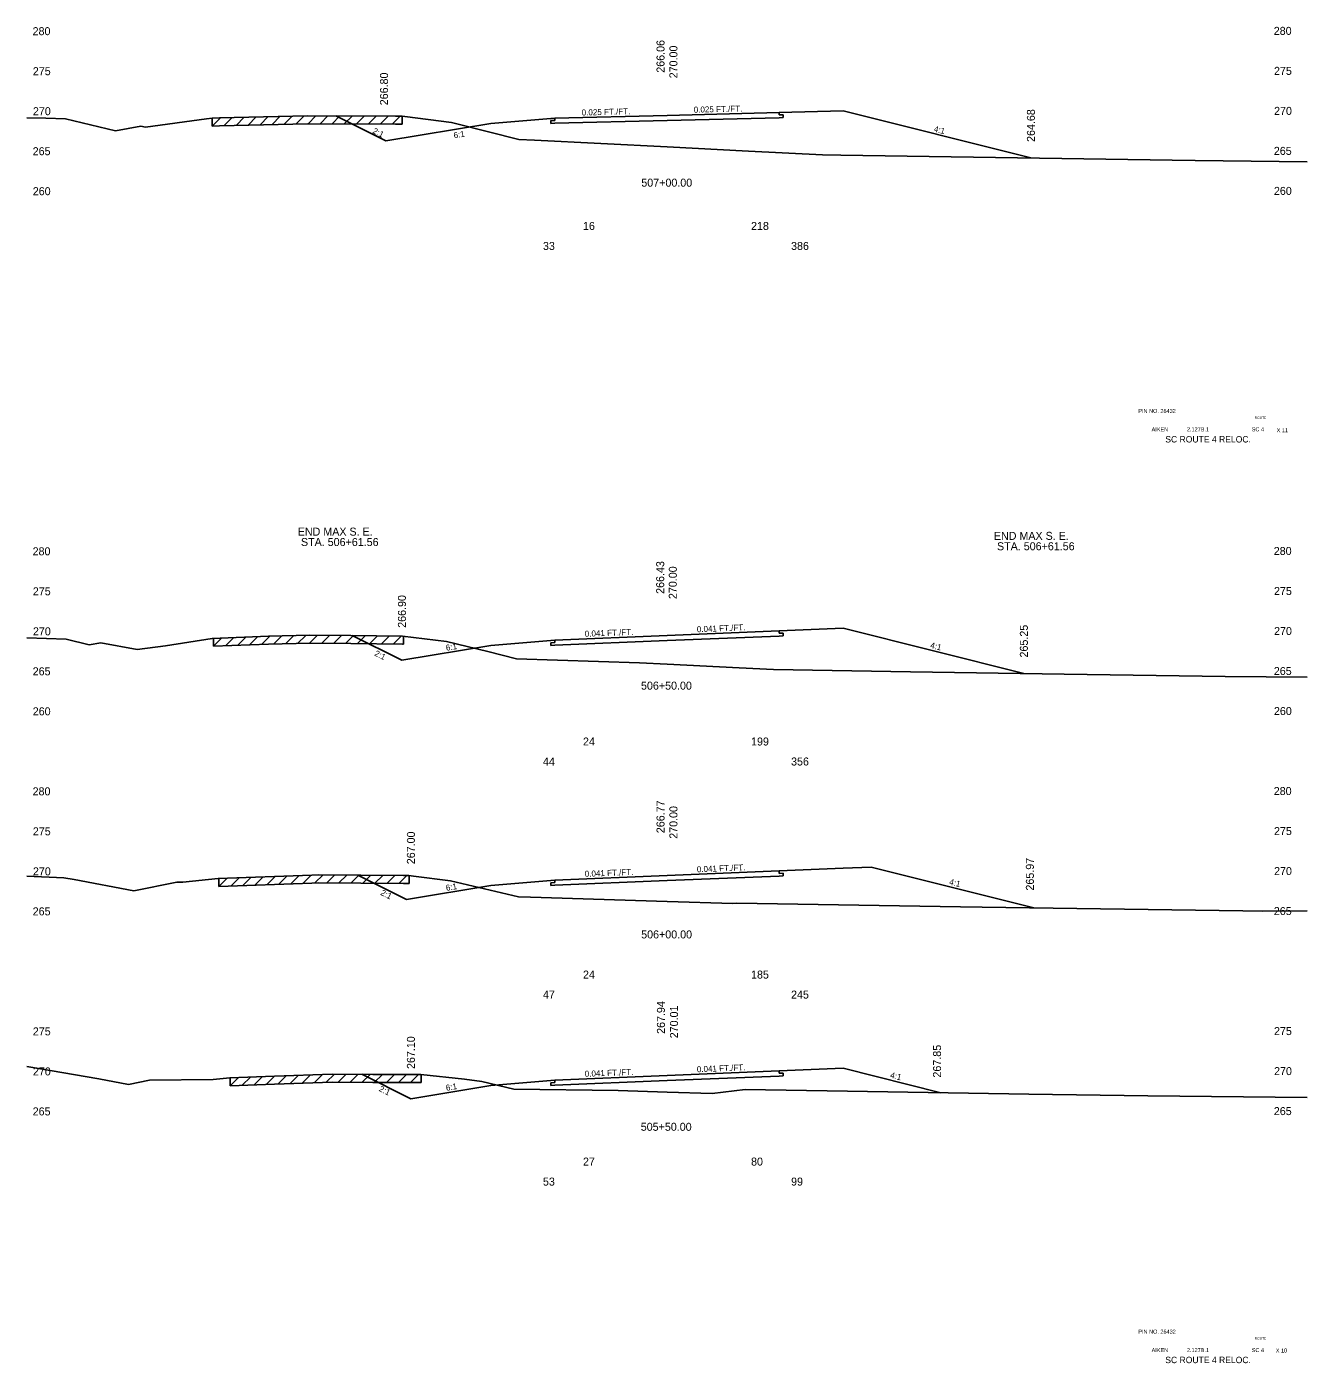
# Model space of a CAD drawing. Extents: x 2967 to 4323, y -3677 to -817.
# Drawn here: x 3188.8 to 3348.8, y -2545.8 to -2378.8 of the extents above; entities that cross this region are included whole.
import ezdxf

# ---------------------------------------------------------------- set-up
doc = ezdxf.new("R2010")
doc.units = 0
for name, color, linetype in [('Level 1', 7, 'Continuous'), ('Level 10', 7, 'Continuous'), ('Level 11', 7, 'Continuous'), ('Level 12', 7, 'Continuous'), ('Level 20', 7, 'Continuous'), ('Level 3', 7, 'Continuous'), ('Level 32', 7, 'Continuous'), ('Level 33', 7, 'Continuous'), ('Level 59', 7, 'Continuous'), ('Level 6', 7, 'Continuous'), ('Level 60', 7, 'Continuous'), ('Level 61', 7, 'Continuous'), ('Level 7', 7, 'Continuous')]:
    doc.layers.add(name, color=color, linetype=linetype)

msp = doc.modelspace()

# ---------------------------------------------------------------- linework, layer by layer
at = {"layer": 'Level 11'}
for p, q in [((3254.76, -2390.19), (3254.76, -2390.49)), ((3282.76, -2389.79), (3282.76, -2389.49)), ((3283.26, -2389.78), (3282.76, -2389.79)), ((3282.76, -2390.13), (3283.26, -2390.12)), ((3283.26, -2390.12), (3283.26, -2389.78)), ((3254.76, -2390.49), (3254.26, -2390.5)), ((3254.26, -2390.5), (3254.26, -2390.84)), ((3254.26, -2390.84), (3254.76, -2390.83)), ((3282.76, -2454.57), (3282.76, -2454.27)), ((3283.26, -2454.55), (3282.76, -2454.57)), ((3282.76, -2454.91), (3283.26, -2454.89)), ((3283.26, -2454.89), (3283.26, -2454.55)), ((3254.76, -2455.72), (3254.26, -2455.74)), ((3254.26, -2455.74), (3254.26, -2456.08)), ((3254.26, -2456.08), (3254.76, -2456.06)), ((3254.76, -2455.42), (3254.76, -2455.72)), ((3254.76, -2485.42), (3254.76, -2485.72)), ((3282.76, -2484.57), (3282.76, -2484.27)), ((3283.26, -2484.55), (3282.76, -2484.57)), ((3282.76, -2484.91), (3283.26, -2484.89)), ((3283.26, -2484.89), (3283.26, -2484.55)), ((3254.76, -2485.72), (3254.26, -2485.74)), ((3254.26, -2485.74), (3254.26, -2486.08)), ((3254.26, -2486.08), (3254.76, -2486.06)), ((3254.76, -2510.41), (3254.76, -2510.71)), ((3282.76, -2509.56), (3282.76, -2509.26)), ((3283.26, -2509.54), (3282.76, -2509.56)), ((3282.76, -2509.9), (3283.26, -2509.88)), ((3283.26, -2509.88), (3283.26, -2509.54)), ((3254.76, -2510.71), (3254.26, -2510.73)), ((3254.26, -2510.73), (3254.26, -2511.07)), ((3254.26, -2511.07), (3254.76, -2511.05))]:
    msp.add_line(p, q, dxfattribs=at)
at = {"layer": 'Level 12'}
for p, q in [((3282.76, -2390.13), (3268.76, -2390.48)), ((3268.76, -2390.48), (3254.76, -2390.83)), ((3282.76, -2454.91), (3268.76, -2455.48)), ((3268.76, -2455.48), (3254.76, -2456.06)), ((3282.76, -2484.91), (3268.76, -2485.48)), ((3268.76, -2485.48), (3254.76, -2486.06)), ((3268.76, -2510.47), (3254.76, -2511.05)), ((3282.76, -2509.9), (3268.76, -2510.47))]:
    msp.add_line(p, q, dxfattribs=at)
at = {"layer": 'Level 59'}
for p, q in [((3254.76, -2390.19), (3268.76, -2389.84)), ((3268.76, -2389.84), (3282.76, -2389.49)), ((3254.76, -2455.42), (3268.76, -2454.84)), ((3268.76, -2454.84), (3282.76, -2454.27)), ((3254.76, -2485.42), (3268.76, -2484.84)), ((3268.76, -2484.84), (3282.76, -2484.27)), ((3254.76, -2510.41), (3268.76, -2509.83)), ((3268.76, -2509.83), (3282.76, -2509.26))]:
    msp.add_line(p, q, dxfattribs=at)
at = {"layer": 'Level 6'}
for p, q in [((3246.76, -2390.86), (3254.76, -2390.19)), ((3282.76, -2389.49), (3290.76, -2389.29)), ((3282.76, -2454.27), (3290.76, -2453.94)), ((3246.76, -2456.08), (3254.76, -2455.42)), ((3246.76, -2486.08), (3254.76, -2485.42)), ((3282.76, -2484.27), (3290.76, -2483.94)), ((3290.76, -2483.94), (3294.26, -2483.8)), ((3246.76, -2511.07), (3254.76, -2510.41)), ((3282.76, -2509.26), (3290.76, -2508.93))]:
    msp.add_line(p, q, dxfattribs=at)
at = {"layer": 'Level 60'}
for p, q in [((3188.76, -2390.14), (3191.14, -2390.18)), ((3191.14, -2390.18), (3193.61, -2390.27)), ((3211.2, -2390.28), (3211.94, -2390.17)), ((3211.94, -2390.17), (3212.83, -2390.13)), ((3212.83, -2390.13), (3223.82, -2389.88)), ((3223.82, -2389.88), (3234.84, -2389.95)), ((3234.84, -2389.95), (3235.65, -2389.95)), ((3235.65, -2389.95), (3235.99, -2390)), ((3235.99, -2390), (3241.85, -2390.73)), ((3193.61, -2390.27), (3199.86, -2391.77)), ((3199.86, -2391.77), (3203.02, -2391.19)), ((3203.02, -2391.19), (3203.6, -2391.3)), ((3203.6, -2391.3), (3211.2, -2390.28)), ((3241.85, -2390.73), (3242.51, -2390.89)), ((3242.51, -2390.89), (3250.25, -2392.87)), ((3250.25, -2392.87), (3252.22, -2392.94)), ((3252.22, -2392.94), (3268.76, -2393.78)), ((3268.76, -2393.78), (3278.95, -2394.3)), ((3278.95, -2394.3), (3288.17, -2394.76)), ((3288.17, -2394.76), (3290.48, -2394.8)), ((3290.48, -2394.8), (3331.87, -2395.43)), ((3331.87, -2395.43), (3334.74, -2395.48)), ((3334.74, -2395.48), (3348.76, -2395.64)), ((3188.76, -2455.13), (3193.67, -2455.32)), ((3193.67, -2455.32), (3196.56, -2456.01)), ((3206.11, -2456.13), (3211.94, -2455.2)), ((3211.94, -2455.2), (3218.96, -2454.94)), ((3218.96, -2454.94), (3224.12, -2454.82)), ((3224.12, -2454.82), (3229.27, -2454.85)), ((3229.27, -2454.85), (3235.7, -2454.91)), ((3235.7, -2454.91), (3238.47, -2455.26)), ((3238.47, -2455.26), (3241.2, -2455.6)), ((3196.56, -2456.01), (3198.02, -2455.74)), ((3198.02, -2455.74), (3202.57, -2456.6)), ((3202.57, -2456.6), (3206.11, -2456.13)), ((3241.2, -2455.6), (3246.37, -2456.83)), ((3246.37, -2456.83), (3249.97, -2457.76)), ((3249.97, -2457.76), (3265.33, -2458.24)), ((3265.33, -2458.24), (3268.76, -2458.41)), ((3268.76, -2458.41), (3277.79, -2458.87)), ((3277.79, -2458.87), (3282.06, -2459.08)), ((3282.06, -2459.08), (3299.19, -2459.37)), ((3299.19, -2459.37), (3318.39, -2459.66)), ((3318.39, -2459.66), (3338.5, -2459.95)), ((3338.5, -2459.95), (3348.76, -2460.07)), ((3188.76, -2484.94), (3193.41, -2485.13)), ((3193.41, -2485.13), (3194.68, -2485.35)), ((3194.68, -2485.35), (3202.14, -2486.76)), ((3208.28, -2485.67), (3212.69, -2485.21)), ((3212.69, -2485.21), (3224.39, -2484.78)), ((3224.39, -2484.78), (3225.16, -2484.75)), ((3225.16, -2484.75), (3235.85, -2484.84)), ((3235.85, -2484.84), (3236.5, -2484.85)), ((3236.5, -2484.85), (3237.1, -2484.91)), ((3237.1, -2484.91), (3241.7, -2485.5)), ((3202.14, -2486.76), (3207.5, -2485.67)), ((3207.5, -2485.67), (3208.28, -2485.67)), ((3241.7, -2485.5), (3250.2, -2487.52)), ((3250.2, -2487.52), (3251.71, -2487.54)), ((3251.71, -2487.54), (3268.76, -2488.08)), ((3268.76, -2488.08), (3276.99, -2488.33)), ((3276.99, -2488.33), (3277.48, -2488.28)), ((3277.48, -2488.28), (3305.44, -2488.74)), ((3305.44, -2488.74), (3308.12, -2488.78)), ((3308.12, -2488.78), (3340.72, -2489.25)), ((3340.72, -2489.25), (3343.13, -2489.28)), ((3343.13, -2489.28), (3348.76, -2489.26)), ((3188.76, -2508.71), (3197.78, -2510.25)), ((3197.78, -2510.25), (3201.46, -2510.94)), ((3201.46, -2510.94), (3204.08, -2510.41)), ((3204.08, -2510.41), (3212.04, -2510.33)), ((3212.04, -2510.33), (3214.14, -2510.11)), ((3214.14, -2510.11), (3219.73, -2509.91)), ((3219.73, -2509.91), (3226.93, -2509.65)), ((3226.93, -2509.65), (3232, -2509.69)), ((3232, -2509.69), (3237.99, -2509.71)), ((3237.99, -2509.71), (3243.46, -2510.31)), ((3243.46, -2510.31), (3245.62, -2510.59)), ((3245.62, -2510.59), (3249.62, -2511.53)), ((3249.62, -2511.53), (3262.64, -2511.71)), ((3262.64, -2511.71), (3268.76, -2511.9)), ((3268.76, -2511.9), (3274.4, -2512.07)), ((3274.4, -2512.07), (3278.53, -2511.6)), ((3278.53, -2511.6), (3291.32, -2511.8)), ((3291.32, -2511.8), (3313.97, -2512.16)), ((3313.97, -2512.16), (3328.82, -2512.36)), ((3328.82, -2512.36), (3348.76, -2512.59))]:
    msp.add_line(p, q, dxfattribs=at)
at = {"layer": 'Level 61'}
for p, q in [((3212.95, -2390.13), (3211.91, -2391.17)), ((3211.91, -2390.17), (3211.91, -2391.17)), ((3214.43, -2390.1), (3213.41, -2391.12)), ((3215.93, -2390.06), (3214.91, -2391.09)), ((3217.43, -2390.03), (3216.41, -2391.05)), ((3218.93, -2389.99), (3217.91, -2391.02)), ((3220.43, -2389.96), (3219.41, -2390.98)), ((3221.93, -2389.93), (3220.91, -2390.95)), ((3223.43, -2389.89), (3222.41, -2390.91)), ((3224.9, -2389.89), (3223.91, -2390.88)), ((3226.4, -2389.9), (3225.41, -2390.89)), ((3227.9, -2389.91), (3226.91, -2390.9)), ((3229.4, -2389.92), (3228.41, -2390.91)), ((3230.9, -2389.92), (3229.91, -2390.92)), ((3232.4, -2389.93), (3231.41, -2390.93)), ((3233.9, -2389.94), (3232.91, -2390.94)), ((3235.4, -2389.95), (3234.41, -2390.95)), ((3235.65, -2390.96), (3235.65, -2389.96)), ((3211.91, -2391.17), (3211.94, -2391.17)), ((3211.94, -2391.17), (3212.83, -2391.13)), ((3212.83, -2391.13), (3223.82, -2390.88)), ((3223.82, -2390.88), (3234.84, -2390.95)), ((3234.84, -2390.95), (3235.65, -2390.95)), ((3235.65, -2390.95), (3235.65, -2390.96)), ((3213.14, -2455.15), (3212.1, -2456.19)), ((3212.1, -2455.19), (3212.1, -2456.19)), ((3214.64, -2455.1), (3213.6, -2456.13)), ((3216.14, -2455.04), (3215.1, -2456.08)), ((3217.64, -2454.98), (3216.6, -2456.02)), ((3219.14, -2454.93), (3218.1, -2455.97)), ((3220.62, -2454.9), (3219.6, -2455.92)), ((3222.12, -2454.86), (3221.1, -2455.89)), ((3223.62, -2454.83), (3222.6, -2455.85)), ((3225.1, -2454.82), (3224.1, -2455.82)), ((3226.59, -2454.83), (3225.6, -2455.83)), ((3228.09, -2454.84), (3227.1, -2455.84)), ((3229.59, -2454.85), (3228.6, -2455.84)), ((3231.09, -2454.86), (3230.1, -2455.86)), ((3232.59, -2454.88), (3231.6, -2455.87)), ((3234.09, -2454.89), (3233.1, -2455.88)), ((3235.59, -2454.9), (3234.6, -2455.9)), ((3235.85, -2455.92), (3235.85, -2454.92)), ((3212.1, -2456.19), (3218.96, -2455.94)), ((3218.96, -2455.94), (3224.12, -2455.82)), ((3224.12, -2455.82), (3229.27, -2455.85)), ((3229.27, -2455.85), (3235.7, -2455.91)), ((3235.7, -2455.91), (3235.85, -2455.92)), ((3213.8, -2485.17), (3212.76, -2486.21)), ((3212.76, -2485.21), (3212.76, -2486.21)), ((3215.3, -2485.11), (3214.26, -2486.15)), ((3216.8, -2485.06), (3215.76, -2486.1)), ((3218.3, -2485), (3217.26, -2486.04)), ((3219.8, -2484.95), (3218.77, -2485.99)), ((3221.3, -2484.89), (3220.27, -2485.93)), ((3222.8, -2484.84), (3221.77, -2485.87)), ((3224.3, -2484.78), (3223.27, -2485.82)), ((3225.78, -2484.75), (3224.77, -2485.76)), ((3227.26, -2484.77), (3226.27, -2485.76)), ((3228.76, -2484.78), (3227.77, -2485.77)), ((3230.26, -2484.79), (3229.27, -2485.79)), ((3231.76, -2484.81), (3230.77, -2485.8)), ((3233.26, -2484.82), (3232.27, -2485.81)), ((3234.76, -2484.83), (3233.77, -2485.82)), ((3236.26, -2484.84), (3235.27, -2485.84)), ((3236.56, -2485.85), (3236.56, -2484.85)), ((3212.76, -2486.21), (3224.39, -2485.78)), ((3224.39, -2485.78), (3225.16, -2485.75)), ((3225.16, -2485.75), (3235.85, -2485.84)), ((3235.85, -2485.84), (3236.5, -2485.85)), ((3236.5, -2485.85), (3236.56, -2485.85)), ((3215.22, -2510.07), (3214.18, -2511.11)), ((3214.18, -2510.11), (3214.18, -2511.11)), ((3216.72, -2510.02), (3215.68, -2511.06)), ((3218.22, -2509.96), (3217.18, -2511)), ((3219.72, -2509.91), (3218.68, -2510.94)), ((3221.22, -2509.85), (3220.18, -2510.89)), ((3222.72, -2509.8), (3221.68, -2510.83)), ((3224.22, -2509.74), (3223.18, -2510.78)), ((3225.72, -2509.69), (3224.69, -2510.73)), ((3227.21, -2509.65), (3226.19, -2510.67)), ((3228.68, -2509.66), (3227.69, -2510.65)), ((3230.18, -2509.67), (3229.19, -2510.67)), ((3231.68, -2509.69), (3230.69, -2510.68)), ((3233.19, -2509.69), (3232.19, -2510.69)), ((3234.69, -2509.7), (3233.69, -2510.7)), ((3236.19, -2509.71), (3235.19, -2510.7)), ((3237.69, -2509.71), (3236.69, -2510.71)), ((3238.04, -2510.72), (3238.04, -2509.72)), ((3214.18, -2511.11), (3219.73, -2510.91)), ((3219.73, -2510.91), (3226.93, -2510.65)), ((3226.93, -2510.65), (3232, -2510.69)), ((3232, -2510.69), (3237.99, -2510.71)), ((3237.99, -2510.71), (3238.04, -2510.72))]:
    msp.add_line(p, q, dxfattribs=at)
at = {"layer": 'Level 7'}
for p, q in [((3227.36, -2389.9), (3233.64, -2393.04)), ((3290.76, -2389.29), (3314.23, -2395.16)), ((3233.64, -2393.04), (3246.76, -2390.86)), ((3229.44, -2454.85), (3235.62, -2457.94)), ((3290.76, -2453.94), (3313.35, -2459.59)), ((3235.62, -2457.94), (3246.76, -2456.08)), ((3230.13, -2484.79), (3236.22, -2487.84)), ((3294.26, -2483.8), (3314.58, -2488.88)), ((3236.22, -2487.84), (3246.76, -2486.08)), ((3230.63, -2509.68), (3236.76, -2512.74)), ((3290.76, -2508.93), (3302.99, -2511.99)), ((3236.76, -2512.74), (3246.76, -2511.07))]:
    msp.add_line(p, q, dxfattribs=at)

# ---------------------------------------------------------------- texts
at = {"layer": 'Level 1'}
for s, p in [('16', (3258.26, -2404.16)), ('218', (3279.26, -2404.16)), ('33', (3253.26, -2406.66)), ('386', (3284.26, -2406.66)), ('END MAX S. E.', (3222.62, -2442.36)), ('END MAX S. E.', (3309.6, -2442.89)), ('STA. 506+61.56', (3223.02, -2443.66)), ('STA. 506+61.56', (3309.99, -2444.19)), ('24', (3258.26, -2468.59)), ('199', (3279.26, -2468.59)), ('44', (3253.26, -2471.09)), ('356', (3284.26, -2471.09)), ('24', (3258.26, -2497.72)), ('185', (3279.26, -2497.72)), ('47', (3253.26, -2500.22)), ('245', (3284.26, -2500.22)), ('27', (3258.26, -2521.09)), ('80', (3279.26, -2521.09)), ('53', (3253.26, -2523.59)), ('99', (3284.26, -2523.59))]:
    msp.add_text(s, height=1, dxfattribs=at).set_placement(p)
at = {"layer": 'Level 10'}
for s, p in [('266.06', (3268.45, -2384.51)), ('266.43', (3268.41, -2449.64)), ('266.77', (3268.45, -2479.55)), ('267.94', (3268.5, -2504.63))]:
    msp.add_text(s, height=1, rotation=90, dxfattribs=at).set_placement(p)
for s, p in [('507+00.00', (3265.55, -2398.75)), ('506+50.00', (3265.51, -2461.61)), ('506+00.00', (3265.53, -2492.7)), ('505+50.00', (3265.48, -2516.74))]:
    msp.add_text(s, height=1, dxfattribs=at).set_placement(p)
at = {"layer": 'Level 20'}
for s, height, p in [('PIN NO. 26432', 0.5, (3327.65, -2427.03)), ('ROUTE', 0.3, (3342.19, -2427.77)), ('AIKEN', 0.5, (3329.31, -2429.33)), ('SC ROUTE 4 RELOC.', 0.8, (3331.02, -2430.72)), (' 2.127B.1', 0.5, (3333.53, -2429.33)), ('SC 4', 0.5, (3341.82, -2429.33)), ('X 11', 0.5, (3344.94, -2429.44)), ('PIN NO. 26432', 0.5, (3327.65, -2542.09)), ('AIKEN', 0.5, (3329.31, -2544.4)), (' 2.127B.1', 0.5, (3333.53, -2544.4)), ('SC 4', 0.5, (3341.82, -2544.4)), ('ROUTE', 0.3, (3342.19, -2542.83)), ('SC ROUTE 4 RELOC.', 0.8, (3331.02, -2545.78)), ('X 10', 0.5, (3344.83, -2544.45))]:
    msp.add_text(s, height=height, dxfattribs=at).set_placement(p)
at = {"layer": 'Level 3'}
for s, p in [(' 280', (3189.12, -2379.82)), (' 280', (3344.2, -2379.78)), (' 275', (3189.15, -2384.82)), (' 275', (3344.23, -2384.78)), (' 270', (3189.16, -2389.82)), (' 270', (3344.24, -2389.78)), (' 265', (3189.13, -2394.82)), (' 265', (3344.21, -2394.78)), (' 260', (3189.14, -2399.82)), (' 260', (3344.22, -2399.78)), (' 280', (3189.12, -2444.82)), (' 280', (3344.2, -2444.78)), (' 275', (3189.15, -2449.82)), (' 275', (3344.23, -2449.78)), (' 270', (3189.16, -2454.82)), (' 270', (3344.24, -2454.78)), (' 265', (3189.13, -2459.82)), (' 265', (3344.21, -2459.78)), (' 260', (3189.14, -2464.82)), (' 260', (3344.22, -2464.78)), (' 280', (3189.12, -2474.82)), (' 280', (3344.2, -2474.78)), (' 275', (3344.23, -2479.78)), (' 275', (3189.15, -2479.82)), (' 270', (3344.24, -2484.78)), (' 270', (3189.16, -2484.82)), (' 265', (3344.21, -2489.78)), (' 265', (3189.13, -2489.82)), (' 275', (3189.15, -2504.82)), (' 275', (3344.23, -2504.78)), (' 270', (3189.16, -2509.82)), (' 270', (3344.24, -2509.78)), (' 265', (3189.13, -2514.82)), (' 265', (3344.21, -2514.78))]:
    msp.add_text(s, height=1, dxfattribs=at).set_placement(p)
at = {"layer": 'Level 32'}
for s, rotation, p in [('0.025 FT./FT.', 1.422, (3258.11, -2389.86)), ('0.025 FT./FT.', 1.4292, (3272.11, -2389.51)), ('2:1', 333.435, (3231.9, -2392.02)), ('6:1', 9.4623, (3242.16, -2392.72)), ('4:1', 345.9638, (3302.04, -2391.86)), ('0.041 FT./FT.', 2.3478, (3272.5, -2454.44)), ('0.041 FT./FT.', 2.3478, (3258.5, -2455.01)), ('2:1', 333.435, (3232.13, -2457.32)), ('6:1', 9.4623, (3241.19, -2456.76)), ('4:1', 345.9638, (3301.6, -2456.39)), ('0.041 FT./FT.', 2.3478, (3272.5, -2484.44)), ('0.041 FT./FT.', 2.3478, (3258.5, -2485.01)), ('4:1', 345.9638, (3303.97, -2485.96)), ('2:1', 333.435, (3232.89, -2487.22)), ('6:1', 9.4623, (3241.19, -2486.76)), ('0.041 FT./FT.', 2.3478, (3272.5, -2509.43)), ('0.041 FT./FT.', 2.3478, (3258.5, -2510)), ('4:1', 345.9638, (3296.59, -2510.11)), ('2:1', 333.435, (3232.7, -2511.74)), ('6:1', 9.4623, (3241.19, -2511.75))]:
    msp.add_text(s, height=0.75, rotation=rotation, dxfattribs=at).set_placement(p)
at = {"layer": 'Level 33'}
for s, p in [('266.80', (3233.9, -2388.58)), ('264.68', (3314.73, -2393.16)), ('266.90', (3236.14, -2453.88)), ('265.25', (3313.85, -2457.59)), ('267.00', (3237.26, -2483.43)), ('265.97', (3314.6, -2486.72)), ('267.10', (3237.26, -2509.02)), ('267.85', (3303, -2510.09))]:
    msp.add_text(s, height=1, rotation=90, dxfattribs=at).set_placement(p)
at = {"layer": 'Level 59'}
for s, p in [(' 270.00', (3270.06, -2385.58)), (' 270.00', (3269.98, -2450.66)), (' 270.00', (3270.06, -2480.62)), (' 270.01', (3270.13, -2505.55))]:
    msp.add_text(s, height=1, rotation=90, dxfattribs=at).set_placement(p)

doc.saveas('drawing.dxf')
